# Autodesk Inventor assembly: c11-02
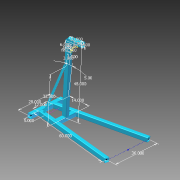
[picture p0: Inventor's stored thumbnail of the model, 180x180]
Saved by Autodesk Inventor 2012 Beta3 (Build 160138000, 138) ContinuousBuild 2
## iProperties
Created: 2011-01
Part Number: c11-02
Document SubType Name: Assembly
Designer: Beta-8540w
_SolveAssemblyDoc: Frame Generator Solve Assembly
_Version: 15.0.0
Author: Beta-8540w
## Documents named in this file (3)
- C:\Inventor 2012 Essentials\Assemblies\Chapter 11\c11-02.iam
- C:\Inventor 2012 Essentials\Parts\Chapter 11\c11-01.ipt
- C:\Inventor 2012 Essentials\Assemblies\Chapter 11\Frame\Frame c11-02.iam
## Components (2 placed, 2 different names)
1. c11-01:1
2. Frame c11-02:1 [sub-assembly]
